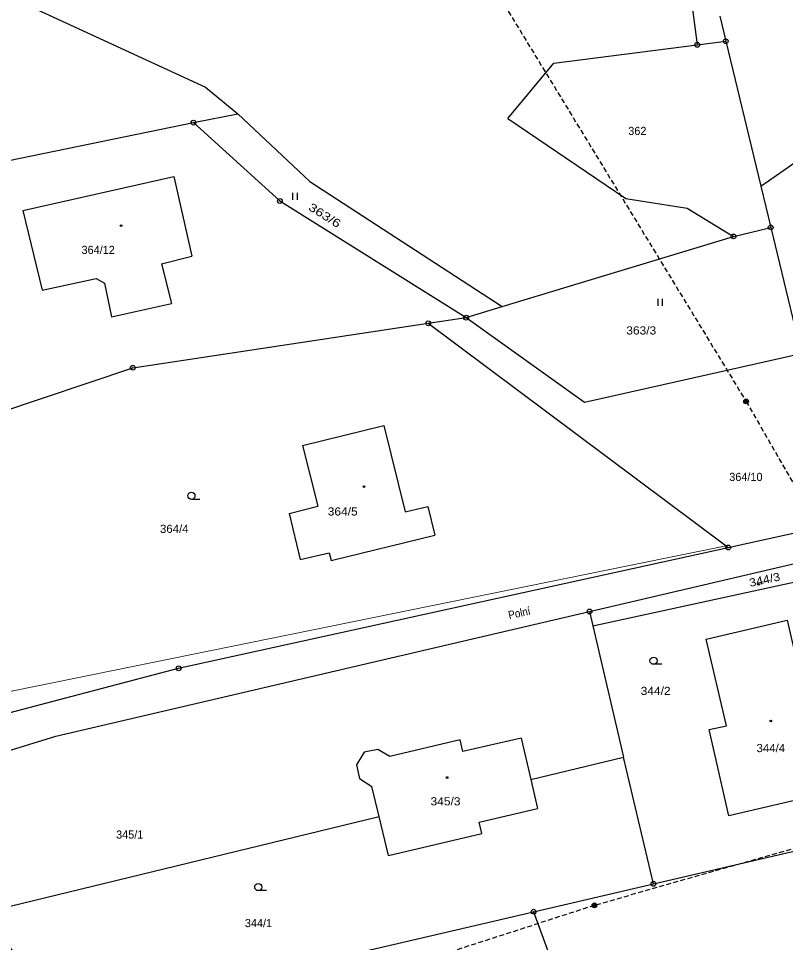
# Model space of a CAD drawing. Extents: x -592965 to -592390, y -1145071 to -1144631.
# Drawn here: x -592769.5 to -592689.4, y -1144977 to -1144880.5 of the extents above; entities that cross this region are included whole.
import ezdxf
from ezdxf.enums import TextEntityAlignment as Align

# ---------------------------------------------------------------- set-up
doc = ezdxf.new("R2010")
doc.units = 0
doc.header["$LTSCALE"] = 0.17
doc.linetypes.add('MEDIUM_DASHED', pattern=[4.5, 3, -1.5])
doc.layers.add('4', color=7, linetype='Continuous', lineweight=25)

msp = doc.modelspace()

# ---------------------------------------------------------------- linework, layer by layer
at = {"layer": '4'}
for p, q in [((-592794.59, -1144867.05), (-592749.94, -1144887.66)), ((-592691.98, -1144897.99), (-592651.29, -1144869.7)), ((-592699.12, -1144879.54), (-592698.61, -1144883.25)), ((-592696.26, -1144880.25), (-592695.63, -1144882.87)), ((-592698.61, -1144883.25), (-592695.63, -1144882.87)), ((-592695.63, -1144882.87), (-592691.98, -1144897.99)), ((-592713.59, -1144885.15), (-592698.61, -1144883.25)), ((-592718.37, -1144890.93), (-592713.59, -1144885.15)), ((-592751.2, -1144891.37), (-592746.58, -1144890.46)), ((-592818.42, -1144905.12), (-592751.2, -1144891.37)), ((-592751.2, -1144891.37), (-592742.17, -1144899.55)), ((-592718.37, -1144890.93), (-592706.07, -1144899.28)), ((-592769.01, -1144900.54), (-592753.23, -1144896.98)), ((-592753.23, -1144896.98), (-592751.35, -1144905.31)), ((-592739.06, -1144897.5), (-592718.96, -1144910.58)), ((-592691.98, -1144897.99), (-592690.94, -1144902.31)), ((-592740.858, -1144898.692), (-592740.858, -1144899.442)), ((-592740.348, -1144899.442), (-592740.348, -1144898.692)), ((-592742.17, -1144899.55), (-592722.73, -1144911.73)), ((-592769.01, -1144900.54), (-592766.98, -1144908.87)), ((-592694.82, -1144903.25), (-592690.94, -1144902.31)), ((-592690.94, -1144902.31), (-592687.76, -1144915.48)), ((-592718.96, -1144910.58), (-592694.82, -1144903.25)), ((-592754.52, -1144906.1), (-592751.35, -1144905.31)), ((-592754.52, -1144906.1), (-592753.48, -1144910.26)), ((-592766.98, -1144908.87), (-592761.34, -1144907.63)), ((-592761.34, -1144907.63), (-592760.48, -1144908.13)), ((-592702.738, -1144909.752), (-592702.738, -1144910.502)), ((-592702.228, -1144910.502), (-592702.228, -1144909.752)), ((-592722.73, -1144911.73), (-592718.96, -1144910.58)), ((-592726.69, -1144912.32), (-592722.73, -1144911.73)), ((-592722.73, -1144911.73), (-592710.37, -1144920.57)), ((-592757.53, -1144916.96), (-592726.69, -1144912.32)), ((-592726.69, -1144912.32), (-592695.58, -1144935.57)), ((-592710.37, -1144920.57), (-592687.76, -1144915.48)), ((-592796.97, -1144930.15), (-592757.53, -1144916.96)), ((-592739.8, -1144925.08), (-592731.31, -1144922.99)), ((-592731.31, -1144922.99), (-592729.09, -1144932)), ((-592739.8, -1144925.08), (-592738.23, -1144931.41)), ((-592750.535, -1144930.7), (-592751.41, -1144930.7)), ((-592741.22, -1144932.17), (-592738.23, -1144931.41)), ((-592741.22, -1144932.17), (-592740.06, -1144936.99)), ((-592729.09, -1144932), (-592726.73, -1144931.43)), ((-592726.73, -1144931.43), (-592726, -1144934.44)), ((-592695.37, -1144935.73), (-592683.65, -1144933.15)), ((-592752.74, -1144948.34), (-592695.37, -1144935.73)), ((-592695.58, -1144935.57), (-592695.37, -1144935.73)), ((-592740.06, -1144936.99), (-592737.02, -1144936.3)), ((-592765.56, -1144955.44), (-592709.85, -1144942.41)), ((-592783.93, -1144956.52), (-592752.74, -1144948.34)), ((-592702.295, -1144947.92), (-592703.17, -1144947.92)), ((-592781.54, -1144960.35), (-592765.56, -1144955.44)), ((-592723.36, -1144955.8), (-592730.69, -1144957.54)), ((-592723.07, -1144957.04), (-592723.36, -1144955.8)), ((-592716.99, -1144955.62), (-592723.07, -1144957.04)), ((-592716.99, -1144955.62), (-592715.98, -1144959.95)), ((-592733.36, -1144957.08), (-592734.19, -1144958.4)), ((-592731.94, -1144956.8), (-592733.36, -1144957.08)), ((-592730.69, -1144957.54), (-592731.94, -1144956.8)), ((-592715.98, -1144959.95), (-592706.29, -1144957.6)), ((-592703.18, -1144970.84), (-592706.29, -1144957.6)), ((-592734.19, -1144958.4), (-592733.87, -1144959.86)), ((-592733.87, -1144959.86), (-592732.59, -1144960.67)), ((-592715.98, -1144959.95), (-592715.28, -1144962.97)), ((-592731.82, -1144963.8), (-592732.59, -1144960.67)), ((-592721.37, -1144964.39), (-592715.28, -1144962.97)), ((-592773.14, -1144973.83), (-592731.82, -1144963.8)), ((-592730.82, -1144967.89), (-592731.82, -1144963.8)), ((-592721.1, -1144965.6), (-592721.37, -1144964.39)), ((-592730.82, -1144967.89), (-592721.1, -1144965.6)), ((-592703.18, -1144970.84), (-592686.45, -1144966.95)), ((-592715.69, -1144973.75), (-592703.18, -1144970.84)), ((-592743.555, -1144971.55), (-592744.43, -1144971.55))]:
    msp.add_line(p, q, dxfattribs=at)
at = {"layer": '4', "lineweight": 13}
msp.add_line((-592691.64, -1144939.4), (-592692.362, -1144939.624), dxfattribs=at)
at = {"layer": '4', "linetype": 'MEDIUM_DASHED'}
msp.add_lwpolyline([(-592857.7, -1144647.96), (-592827.25, -1144698.04), (-592798.73, -1144745.3), (-592765.1, -1144800.74), (-592721.92, -1144873.86), (-592693.51, -1144920.47), (-592669.72, -1144961.82), (-592709.34, -1144973.09), (-592761.29, -1144989.89), (-592825.83, -1145034.08), (-592878.88, -1145071.17)], dxfattribs=at)
at = {"layer": '4'}
for points in [[(-592749.94, -1144887.66), (-592746.58, -1144890.46), (-592739.06, -1144897.5)], [(-592706.07, -1144899.28), (-592699.65, -1144900.3), (-592694.82, -1144903.25)], [(-592760.48, -1144908.13), (-592759.75, -1144911.63), (-592753.48, -1144910.26)], [(-592737.02, -1144936.3), (-592736.83, -1144937.09), (-592726, -1144934.44)], [(-592709.85, -1144942.41), (-592686.06, -1144936.85), (-592682.2, -1144935.31)], [(-592709.5, -1144943.92), (-592681.5, -1144937.82), (-592682.2, -1144935.31)], [(-592709.85, -1144942.41), (-592709.5, -1144943.92), (-592706.29, -1144957.6)], [(-592773.14, -1144973.83), (-592764.58, -1144985.13), (-592715.69, -1144973.75)], [(-592715.69, -1144973.75), (-592707.19, -1144997), (-592705.13, -1145002.64)]]:
    msp.add_lwpolyline(points, dxfattribs=at)
at = {"layer": '4', "lineweight": 13}
for points in [[(-592785.15, -1144954.05), (-592784.23, -1144953.58), (-592695.58, -1144935.57)], [(-592692.084, -1144939.67), (-592692.362, -1144939.624), (-592692.159, -1144939.429)]]:
    msp.add_lwpolyline(points, dxfattribs=at)
at = {"layer": '4'}
msp.add_lwpolyline([(-592682.91, -1144960.84), (-592695.32, -1144963.74), (-592697.38, -1144954.72), (-592695.57, -1144954.34), (-592697.68, -1144945.28), (-592689.24, -1144943.33), (-592687.12, -1144952.37), (-592684.94, -1144951.85)], close=True, dxfattribs=at)
for centre, radius in [((-592698.61, -1144883.25), 0.25), ((-592695.63, -1144882.87), 0.25), ((-592695.63, -1144882.87), 0.0164), ((-592698.61, -1144883.25), 0.0164), ((-592751.2, -1144891.37), 0.25), ((-592751.2, -1144891.37), 0.0164), ((-592742.17, -1144899.55), 0.25), ((-592742.17, -1144899.55), 0.0164), ((-592758.75, -1144902.13), 0.0875), ((-592690.94, -1144902.31), 0.25), ((-592690.94, -1144902.31), 0.0164), ((-592694.82, -1144903.25), 0.25), ((-592694.82, -1144903.25), 0.0164), ((-592726.69, -1144912.32), 0.25), ((-592722.73, -1144911.73), 0.25), ((-592722.73, -1144911.73), 0.0164), ((-592726.69, -1144912.32), 0.0164), ((-592757.53, -1144916.96), 0.25), ((-592757.53, -1144916.96), 0.0164), ((-592693.51, -1144920.47), 0.25), ((-592693.51, -1144920.47), 0.15), ((-592693.51, -1144920.47), 0.075), ((-592733.39, -1144929.36), 0.0875), ((-592751.41, -1144930.325), 0.375), ((-592695.37, -1144935.73), 0.25), ((-592695.37, -1144935.73), 0.0164), ((-592709.85, -1144942.41), 0.25), ((-592709.85, -1144942.41), 0.0164), ((-592703.17, -1144947.545), 0.375), ((-592752.74, -1144948.34), 0.25), ((-592752.74, -1144948.34), 0.0164), ((-592690.93, -1144953.84), 0.0875), ((-592724.72, -1144959.74), 0.0875), ((-592744.43, -1144971.175), 0.375), ((-592703.18, -1144970.84), 0.25), ((-592703.18, -1144970.84), 0.0164), ((-592709.34, -1144973.09), 0.25), ((-592715.69, -1144973.75), 0.25), ((-592715.69, -1144973.75), 0.0164), ((-592709.34, -1144973.09), 0.15), ((-592709.34, -1144973.09), 0.075)]:
    msp.add_circle(centre, radius, dxfattribs=at)

# ---------------------------------------------------------------- texts
for s, p in [('362', (-592705.81, -1144892.66)), ('364/12', (-592762.88, -1144905.08)), ('364/10', (-592695.27, -1144928.78)), ('345/1', (-592759.27, -1144966.12)), ('344/1', (-592745.829, -1144975.36))]:
    msp.add_text(s, height=0.85, dxfattribs=at).set_placement(p)
for s, height, rotation, width, p in [('363/6', 0.85, 327.746, 1.3, (-592739.28, -1144900.42)), ('344/3', 0.85, 12.29, 1.15, (-592693.085, -1144939.849)), ('344/3', 0.1, 12.29, 1.3, (-592691.64, -1144939.4))]:
    msp.add_text(s, height=height, rotation=rotation, dxfattribs=dict(at, width=width)).set_placement(p)
for s, width, p in [('363/3', 1.1, (-592706.02, -1144913.49)), ('364/5', 1.1, (-592737.18, -1144932.39)), ('364/4', 1.05, (-592754.69, -1144934.2)), ('344/2', 1.1, (-592704.516, -1144951.12)), ('344/4', 1.05, (-592692.423, -1144957.09)), ('345/3', 1.1, (-592726.452, -1144962.65))]:
    msp.add_text(s, height=0.85, dxfattribs=dict(at, width=width)).set_placement(p)
at = {"layer": '4', "width": 0.9}
msp.add_text('Polní', height=0.85, rotation=12.125, dxfattribs=at).set_placement((-592717.0913, -1144942.976), align=Align.CENTER)

doc.saveas('drawing.dxf')
